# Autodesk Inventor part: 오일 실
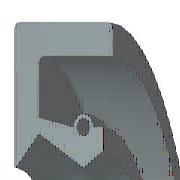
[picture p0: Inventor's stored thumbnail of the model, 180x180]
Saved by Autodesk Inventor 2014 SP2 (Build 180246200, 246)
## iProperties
IsCustomPart: 0
Created: 2014-10
Part Number: 오일 실
Material: 고무
Description: 오일-실
Document SubType Name: Modeling
Standard: KS B 2804
Designer: KYOUNG IL JANG
Standards Organization: KS
Language: ko-KR
Size Designation: D - 17 32 8
Categories: <MemberInstance><Categories><Category DisplayName="샤프트 부품" InternalName="7f7aeb1f-a693-4053-b835-cee3144e0d98" Mnemonic="SHFT"><Category DisplayName="실링" Intern
Density: 0.93 g/cm^3
Mass: 2.28027 g
Surface Area: 32.1224 cm^2
Volume: 2.45191 cm^3
Appearance: 고무 - 검은색 - 버전 1.1
Author: SeoGD™ [www.esajin.kr]
Revision Number: 1
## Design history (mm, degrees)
revolve "본체" stored, may be unused: angle "d17" = 90 deg
revolve "스프링1" stored, may be unused: angle "d18" = 90 deg
body "Solid1"
sketch "스케치1"
  geometry: L1 (0, 16)-(8, 16); L2 (8, 14.25)-(1.75, 14.25); L3 (1.75, 10.25)-(4.9, 8.5); L4 (4.9, 8.5)-(0, 8.5); L5 (0, 0)-(9.586, 0) reference; L6 (4.9, 8.5)-(6.3, 9.375); L7 (0, 18)-(0, -3) reference; L8 (-1.941, 0)-(11.507, 0) reference; L9 (4.2, 10.6)-(1.75, 11.21); L10 (1.75, 11.21)-(1.75, 14.25); L11 (0, 16)-(0, 8.588); L12 (4.9, 8.5)-(0, 8.5); L13 (1.75, 10.25)-(0.152, 8.528); L14 (8, 16)-(8, 14.25); L15 (5.6, 10.6)-(6.3, 10.6); L16 (6.3, 10.6)-(6.3, 9.375); C1 r 0.455 at (4.9, 10.6); A1 r 0.7 centre (4.9, 10.6) between (5.6, 10.6) and (4.2, 10.6); A2 r 0.088 centre (0.088, 8.588) between (0, 8.588) and (0.152, 8.528); 1 further point
  constraints: 28 end point, 5 horizontal alignment, 5 point on line, 4 point on circle, 4 vertical alignment, 3 centre point, 3 tangent, 2 collinear, 2 horizontal, 2 perpendicular, 1 coincident, 1 parallel
  dimensions: "d0" = 32 diameter of L1 L5 (= SD2); "d1" = 1.75 distance of L1.end L2.start (= SD); "d2" = 0.91 diameter of C1 (= SPDI); "d3" = 1.4 diameter of A1 (= SPDA); "d4" = 17 diameter of L3.end L5 (= NND); "d5" = 20.5 diameter of L3.start L5 (= TKDM); "d7" = 22.42 diameter of L9.end L5 (= TKDM + 0.24 x SWDT); "d8" = 1.75 distance between parallel lines of L11 L10 (= SD); "d9" = 4.9 distance from line of L11 C1.centre (= SPDST); "d10" = 21.2 diameter of C1.centre L5 (= HLDM); "d11" = 0.0875 radius of A2 (= 0.25 x LAB); "d12" = 6.3 distance between parallel lines of L11 L16 (= SDI); "d13" = 18.75 diameter of L6.end L5 (= ABDM); "d14" = 8 distance from line of L11 L1.end (= SWDT)
fillet "모깎기1" dims "d6" = 0.3 (= RR)
other parameters: "SD2" = 32 [user parameter; used in 1 equation term], "SWDT" = 8 [user parameter; used in 2 equation terms], "RR" = 0.3 [user parameter; used in 1 equation term], "SD" = 1.75 [user parameter; used in 2 equation terms], "NND" = 17 [user parameter; used in 1 equation term], "SPDA" = 1.4 [user parameter; used in 1 equation term], "SPDI" = 0.91 [user parameter; used in 1 equation term], "TKDM" = 20.5 [user parameter; used in 2 equation terms], "HLDM" = 21.2 [user parameter; used in 1 equation term], "ABDM" = 18.75 [user parameter; used in 1 equation term], "SDI" = 6.3 [user parameter; used in 1 equation term], "SPDST" = 4.9 [user parameter; used in 1 equation term], "LAB" = 0.35 [user parameter; used in 1 equation term], "d15" = 0, "d16" = 0, "d19" = 0
